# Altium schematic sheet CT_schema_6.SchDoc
size 274 x 160 mm
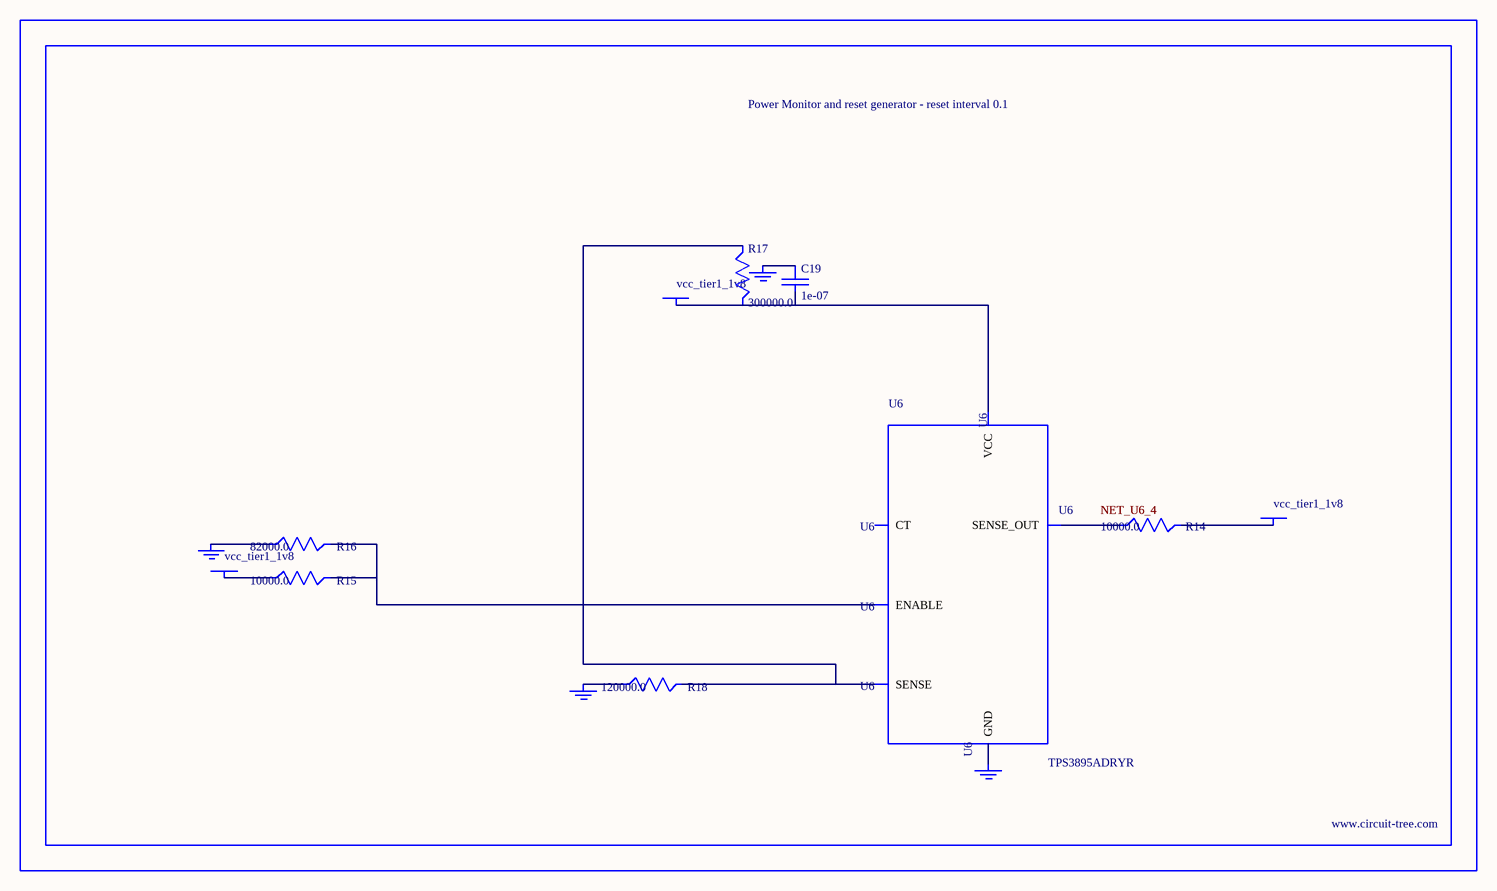
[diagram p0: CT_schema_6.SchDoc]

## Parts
BORDER5  (no value)
C19  1e-07  [C0402]
GND_INSTANCE_5_0  (no value)
GND_INSTANCE_5_1  (no value)
GND_INSTANCE_5_2  (no value)
GND_INSTANCE_5_3  (no value)
POWER_INSTANCE_5_0  vcc_tier1_1v8
POWER_INSTANCE_5_1  vcc_tier1_1v8
POWER_INSTANCE_5_2  vcc_tier1_1v8
R14  10000.0  [R0603]
R15  10000.0  [R0603]
R16  82000.0  [R0603]
R17  300000.0  [R0603]
R18  120000.0  [R0603]
U6  TPS3895ADRYR  [SON-6]

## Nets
NetC19_1: C19.1 GND_INSTANCE_5_2.0(GND)
NetC19_2: C19.2 POWER_INSTANCE_5_2.0(PWR) R17.2 U6.6(VCC)
NetGND_INSTANCE_5_0_0: GND_INSTANCE_5_0.0(GND) R16.1
NetGND_INSTANCE_5_1_0: GND_INSTANCE_5_1.0(GND) R18.1
NetGND_INSTANCE_5_3_0: GND_INSTANCE_5_3.0(GND) U6.2(GND)
NetPOWER_INSTANCE_5_0_0: POWER_INSTANCE_5_0.0(PWR) R15.1
NetPOWER_INSTANCE_5_1_0: POWER_INSTANCE_5_1.0(PWR) R14.2
NetR14_1: R14.1 U6.4(SENSE_OUT)
NetR15_2: R15.2 R16.2 U6.1(ENABLE)
NetR17_1: R17.1 R18.2 U6.3(SENSE)

Not connected (* = marked no-connect by the designer): U6 5(CT)

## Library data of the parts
BORDER5 = BORDER_PAGE5
C19 = C0402C104K3RACTU
GND_INSTANCE_5_0-GND_INSTANCE_5_3 = GND
POWER_INSTANCE_5_0-POWER_INSTANCE_5_2 = PWR
R14 R15 = RC0603JR-0710KL
R16 = RC0603JR-0782KL
R17 = RC0603JR-07300KL
R18 = RC0603JR-07120KL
